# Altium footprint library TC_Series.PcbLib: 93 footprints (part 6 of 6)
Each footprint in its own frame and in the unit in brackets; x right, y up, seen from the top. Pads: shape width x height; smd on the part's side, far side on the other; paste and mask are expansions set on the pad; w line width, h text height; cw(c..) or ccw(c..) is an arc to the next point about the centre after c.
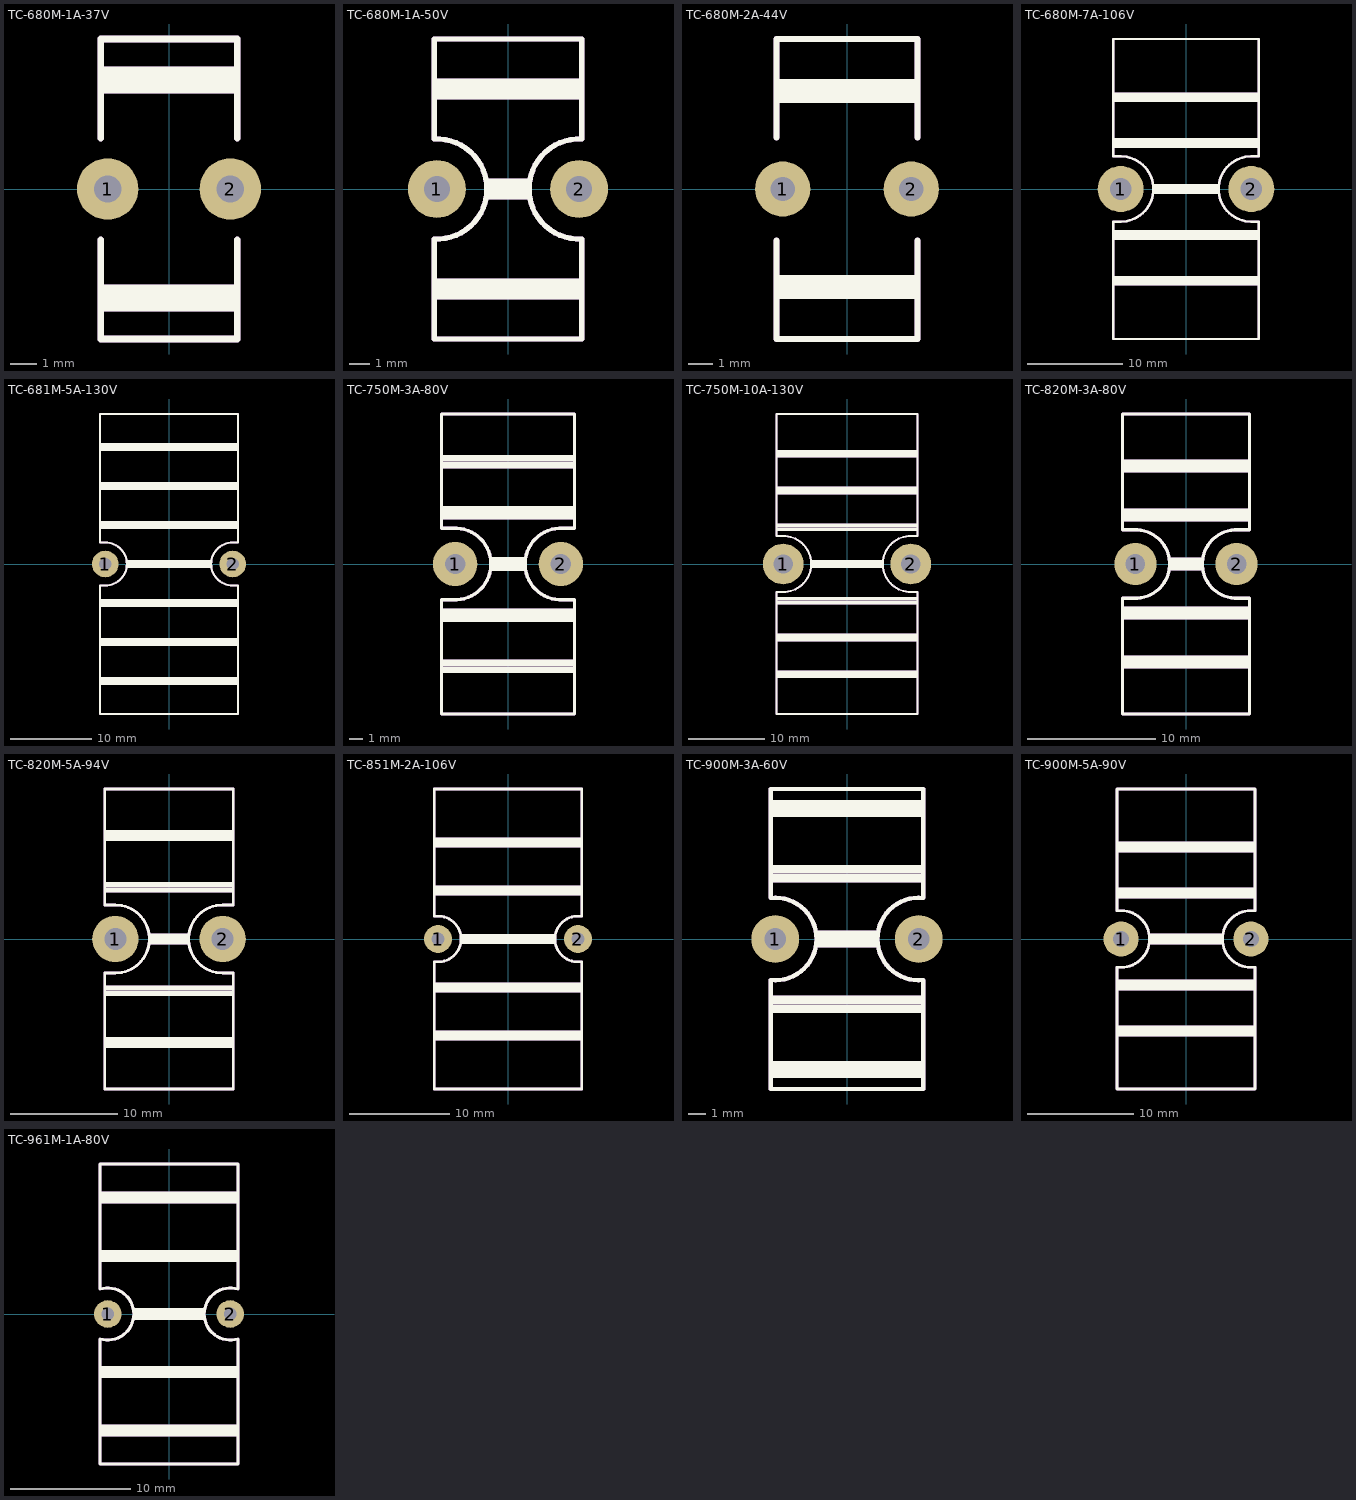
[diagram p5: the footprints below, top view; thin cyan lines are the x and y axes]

## TC-680M-1A-37V [mil]
pads (2):
  round 90 hole 40: 1(-90,0) 2(90,0)
Top Overlay:
  lines w10: -100,-74.78 -100,-220 100,-220 100,-74.78 ; -100,74.78 -100,220 100,220 100,74.78
  lines w19.68: -95,-170 95,-170 ; -95,-150 95,-150 ; -95,150 95,150 ; -95,170 95,170
Mechanical 29:
  lines w10: -100,-74.78 -100,-220 100,-220 100,-74.78 ; -100,74.78 -100,220 100,220 100,74.78
  lines w19.68: -95,-170 95,-170 ; -95,-150 95,-150 ; -95,150 95,150 ; -95,170 95,170
  text "'.Designator'" at -785,-42.45 h200

## TC-680M-1A-50V [mil]
pads (2):
  round 110 hole 50: 1(-135,0) 2(135,0)
Top Overlay:
  lines w10: 140,-95 140,-285 -140,-285 -140,-94.87 ccw(c-135,0) -139.99,94.87 -140,285 140,285 140,95 ; 139.99,-94.87 cw(c135,0) 139.99,94.87
  lines w19.68: -135,-200 135,-200 ; -135,-180 135,-180 ; -135,180 135,180 ; -135,200 135,200 ; -35,-10 35,-10 ; -35,10 35,10
Mechanical 29:
  lines w10: 140,-95 140,-285 -140,-285 -140,-94.87 ccw(c-135,0) -139.99,94.87 -140,285 140,285 140,95 ; 139.99,-94.87 cw(c135,0) 139.99,94.87
  lines w19.68: -135,-200 135,-200 ; -135,-180 135,-180 ; -135,180 135,180 ; -135,200 135,200 ; -35,-10 35,-10 ; -35,10 35,10
  text "'.Designator'" at -1750,-64.85 h400

## TC-680M-2A-44V [mil]
pads (2):
  round 90 hole 40: 1(-105,0) 2(105,0)
Top Overlay:
  lines w10: -115,-84.42 -115,-245 115,-245 115,-84.42 ; -115,84.42 -115,245 115,245 115,84.42
  lines w19.68: -110,-170 110,-170 ; -110,-150 110,-150 ; -110,150 110,150 ; -110,170 110,170
Mechanical 29:
  lines w10: -115,-84.42 -115,-245 115,-245 115,-84.42 ; -115,84.42 -115,245 115,245 115,84.42
  lines w19.68: -110,-170 110,-170 ; -110,-150 110,-150 ; -110,150 110,150 ; -110,170 110,170
  text "'.Designator'" at -1750,-64.85 h400

## TC-680M-7A-106V [mil]
pads (2):
  round 190 hole 90: 1(-270,0) 2(270,0)
Top Overlay:
  lines w10: -300,-620 300,-620 300,-135 270,-135 cw(c270,0) 270,135 300,135 300,620 -300,620 -300,135 -270,135 cw(c-270,0) -270,-135 -300,-135 -300,-620
  lines w19.68: -295,-390 295,-390 ; -295,-370 295,-370 ; -295,-200 295,-200 ; -295,-180 295,-180 ; -295,180 295,180 ; -295,200 295,200 ; -295,370 295,370 ; -295,390 295,390 ; -130,-10 130,-10 ; -130,10 130,10
Mechanical 29:
  lines w10: -300,-620 300,-620 300,-135 270,-135 cw(c270,0) 270,135 300,135 300,620 -300,620 -300,135 -270,135 cw(c-270,0) -270,-135 -300,-135 -300,-620
  lines w19.68: -295,-390 295,-390 ; -295,-370 295,-370 ; -295,-200 295,-200 ; -295,-180 295,-180 ; -295,180 295,180 ; -295,200 295,200 ; -295,370 295,370 ; -295,390 295,390 ; -130,-10 130,-10 ; -130,10 130,10
  text "'.Designator'" at -1750,-64.85 h400

## TC-681M-5A-130V [mil]
pads (2):
  round 130 hole 60: 1(-310,0) 2(310,0)
Top Overlay:
  lines w10: -335,-730 335,-730 335,-105 310,-105 cw(c310,0) 310,105 335,105 335,730 -335,730 -335,105 -310,105 cw(c-310,0) -310,-105 -335,-105 -335,-730
  lines w19.68: -330,-580 330,-580 ; -330,-560 330,-560 ; -330,-390 330,-390 ; -330,-370 330,-370 ; -330,-200 330,-200 ; -330,-180 330,-180 ; -330,180 330,180 ; -330,200 330,200 ; -330,370 330,370 ; -330,390 330,390 ; -330,560 330,560 ; -330,580 330,580 ; -200,-10 200,-10 ; -200,10 200,10
Mechanical 29:
  lines w10: -335,-730 335,-730 335,-105 310,-105 cw(c310,0) 310,105 335,105 335,730 -335,730 -335,105 -310,105 cw(c-310,0) -310,-105 -335,-105 -335,-730
  lines w19.68: -330,-580 330,-580 ; -330,-560 330,-560 ; -330,-390 330,-390 ; -330,-370 330,-370 ; -330,-200 330,-200 ; -330,-180 330,-180 ; -330,180 330,180 ; -330,200 330,200 ; -330,370 330,370 ; -330,390 330,390 ; -330,560 330,560 ; -330,580 330,580 ; -200,-10 200,-10 ; -200,10 200,10
  text "'.Designator'" at -1750,-64.85 h400

## TC-750M-3A-80V [mil]
pads (2):
  round 130 hole 60: 1(-155,0) 2(155,0)
Top Overlay:
  lines w10: -195,-105 -195,-440 195,-440 195,-105 ; -195,105 -195,440 195,440 195,105 ; -194.85,-104.85 -160.52,-104.85 ccw(c-155,0) -160.52,104.85 -194.85,104.85 ; 194.85,-104.85 160.52,-104.85 cw(c155,0) 160.52,104.85 194.85,104.85
  lines w19.68: -190,-310 190,-310 ; -190,-290 190,-290 ; -190,-160 190,-160 ; -190,-140 190,-140 ; -190,140 190,140 ; -190,160 190,160 ; -190,290 190,290 ; -190,310 190,310 ; -45,-10 45,-10 ; -45,10 45,10
Mechanical 29:
  lines w10: -195,-105 -195,-440 195,-440 195,-105 ; -195,105 -195,440 195,440 195,105 ; -194.85,-104.85 -160.52,-104.85 ccw(c-155,0) -160.52,104.85 -194.85,104.85 ; 194.85,-104.85 160.52,-104.85 cw(c155,0) 160.52,104.85 194.85,104.85
  lines w19.68: -190,-310 190,-310 ; -190,-290 190,-290 ; -190,-160 190,-160 ; -190,-140 190,-140 ; -190,140 190,140 ; -190,160 190,160 ; -190,290 190,290 ; -190,310 190,310 ; -45,-10 45,-10 ; -45,10 45,10
  text "'.Designator'" at -1750,-64.85 h400

## TC-750M-10A-130V [mil]
pads (2):
  round 210 hole 100: 1(-330,0) 2(330,0)
Top Overlay:
  lines w10: -365,-775 -365,-145 -330,-145 ccw(c-330,0) -330,145 -365,145 -365,775 365,775 365,145 330,145 ccw(c330,0) 330,-145 365,-145 365,-775 -365,-775
  lines w19.68: -360,-580 360,-580 ; -360,-560 360,-560 ; -360,-390 360,-390 ; -360,-370 360,-370 ; -360,-200 360,-200 ; -360,-180 360,-180 ; -360,180 360,180 ; -360,200 360,200 ; -360,370 360,370 ; -360,390 360,390 ; -360,560 360,560 ; -360,580 360,580 ; -180,-10 180,-10 ; -180,10 180,10
Mechanical 29:
  lines w10: -365,-775 -365,-145 -330,-145 ccw(c-330,0) -330,145 -365,145 -365,775 365,775 365,145 330,145 ccw(c330,0) 330,-145 365,-145 365,-775 -365,-775
  lines w19.68: -360,-580 360,-580 ; -360,-560 360,-560 ; -360,-390 360,-390 ; -360,-370 360,-370 ; -360,-200 360,-200 ; -360,-180 360,-180 ; -360,180 360,180 ; -360,200 360,200 ; -360,370 360,370 ; -360,390 360,390 ; -360,560 360,560 ; -360,580 360,580 ; -180,-10 180,-10 ; -180,10 180,10
  text "'.Designator'" at -1750,-64.85 h400

## TC-820M-3A-80V [mil]
pads (2):
  round 130 hole 60: 1(-155,0) 2(155,0)
Top Overlay:
  lines w10: -195,-105 -195,-460 195,-460 195,-105 ; -195,105 -195,460 195,460 195,105 ; -194.85,-104.85 -160.52,-104.85 ccw(c-155,0) -160.52,104.85 -194.85,104.85 ; 194.85,-104.85 160.52,-104.85 cw(c155,0) 160.52,104.85 194.85,104.85
  lines w19.68: -190,-310 190,-310 ; -190,-290 190,-290 ; -190,-160 190,-160 ; -190,-140 190,-140 ; -190,140 190,140 ; -190,160 190,160 ; -190,290 190,290 ; -190,310 190,310 ; -45,-10 45,-10 ; -45,10 45,10
Mechanical 29:
  lines w10: -195,-105 -195,-460 195,-460 195,-105 ; -195,105 -195,460 195,460 195,105 ; -194.85,-104.85 -160.52,-104.85 ccw(c-155,0) -160.52,104.85 -194.85,104.85 ; 194.85,-104.85 160.52,-104.85 cw(c155,0) 160.52,104.85 194.85,104.85
  lines w19.68: -190,-310 190,-310 ; -190,-290 190,-290 ; -190,-160 190,-160 ; -190,-140 190,-140 ; -190,140 190,140 ; -190,160 190,160 ; -190,290 190,290 ; -190,310 190,310 ; -45,-10 45,-10 ; -45,10 45,10
  text "'.Designator'" at -1750,-64.85 h400

## TC-820M-5A-94V [mil]
pads (2):
  round 170 hole 80: 1(-197,0) 2(197,0)
Top Overlay:
  lines w10: -236,-551 236,-551 236,-125 197,-125 cw(c197,0) 197,125 236,125 236,551 -236,551 -236,125 -197,125 cw(c-197,0) -197,-125 -236,-125 -236,-551
  lines w19.68: -230,-390 230,-390 ; -230,-370 230,-370 ; -230,-200 230,-200 ; -230,-180 230,-180 ; -230,180 230,180 ; -230,200 230,200 ; -230,370 230,370 ; -230,390 230,390 ; -67,-10 68,-10 ; -67,10 68,10
Mechanical 29:
  lines w10: -236,-551 236,-551 236,-125 197,-125 cw(c197,0) 197,125 236,125 236,551 -236,551 -236,125 -197,125 cw(c-197,0) -197,-125 -236,-125 -236,-551
  lines w19.68: -230,-390 230,-390 ; -230,-370 230,-370 ; -230,-200 230,-200 ; -230,-180 230,-180 ; -230,180 230,180 ; -230,200 230,200 ; -230,370 230,370 ; -230,390 230,390 ; -67,-10 68,-10 ; -67,10 68,10
  text "'.Designator'" at -1750,-64.85 h400

## TC-851M-2A-106V [mil]
pads (2):
  round 110 hole 50: 1(-275,0) 2(275,0)
Top Overlay:
  lines w10: 290,88.63 290,590 -290,590 -290,88.74 cw(c-275,0) -290,-88.74 -290,-590 290,-590 290,-88.74 cw(c275,0) 290,88.74
  lines w19.68: -285,-390 285,-390 ; -285,-370 285,-370 ; -285,-200 285,-200 ; -285,-180 285,-180 ; -285,180 285,180 ; -285,200 285,200 ; -285,370 285,370 ; -285,390 285,390 ; -180,-10 180,-10 ; -180,10 180,10
Mechanical 29:
  lines w10: 290,88.63 290,590 -290,590 -290,88.74 cw(c-275,0) -290,-88.74 -290,-590 290,-590 290,-88.74 cw(c275,0) 290,88.74
  lines w19.68: -285,-390 285,-390 ; -285,-370 285,-370 ; -285,-200 285,-200 ; -285,-180 285,-180 ; -285,180 285,180 ; -285,200 285,200 ; -285,370 285,370 ; -285,390 285,390 ; -180,-10 180,-10 ; -180,10 180,10
  text "'.Designator'" at -1750,-64.85 h400

## TC-900M-3A-60V [mil]
pads (2):
  round 110 hole 50: 1(-165,0) 2(165,0)
Top Overlay:
  lines w10: -175,-94.48 -175,-345 175,-345 175,-95 ; -175,-94.47 ccw(c-165,0) -174.95,94.48 ; -175,94.48 -175,345 175,345 175,95 ; 174.95,-94.48 cw(c165,0) 174.93,94.48
  lines w19.68: -170,-310 170,-310 ; -170,-290 170,-290 ; -170,-160 170,-160 ; -170,-140 170,-140 ; -170,140 170,140 ; -170,160 170,160 ; -170,290 170,290 ; -170,310 170,310 ; -65,-10 65,-10 ; -65,10 65,10
Mechanical 29:
  lines w10: -175,-94.48 -175,-345 175,-345 175,-95 ; -175,-94.47 ccw(c-165,0) -174.95,94.48 ; -175,94.48 -175,345 175,345 175,95 ; 174.95,-94.48 cw(c165,0) 174.93,94.48
  lines w19.68: -170,-310 170,-310 ; -170,-290 170,-290 ; -170,-160 170,-160 ; -170,-140 170,-140 ; -170,140 170,140 ; -170,160 170,160 ; -170,290 170,290 ; -170,310 170,310 ; -65,-10 65,-10 ; -65,10 65,10
  text "'.Designator'" at -1750,-64.85 h400

## TC-900M-5A-90V [mil]
pads (2):
  round 130 hole 60: 1(-240,0) 2(240,0)
Top Overlay:
  lines w10: -255,-555 255,-555 255,-105 240,-105 cw(c240,0) 240,105 255,105 255,555 -255,555 -255,105 -240,105 cw(c-240,0) -240,-105 -255,-105 -255,-555
  lines w19.68: -250,-350 250,-350 ; -250,-330 250,-330 ; -250,-180 250,-180 ; -250,-160 250,-160 ; -250,160 250,160 ; -250,180 250,180 ; -250,330 250,330 ; -250,350 250,350 ; -130,-10 130,-10 ; -130,10 130,10
Mechanical 29:
  lines w10: -255,-555 255,-555 255,-105 240,-105 cw(c240,0) 240,105 255,105 255,555 -255,555 -255,105 -240,105 cw(c-240,0) -240,-105 -255,-105 -255,-555
  lines w19.68: -250,-350 250,-350 ; -250,-330 250,-330 ; -250,-180 250,-180 ; -250,-160 250,-160 ; -250,160 250,160 ; -250,180 250,180 ; -250,330 250,330 ; -250,350 250,350 ; -130,-10 130,-10 ; -130,10 130,10
  text "'.Designator'" at -1750,-64.85 h400

## TC-961M-1A-80V [mil]
pads (2):
  round 90 hole 42: 1(-200,0) 2(200,0)
Top Overlay:
  lines w10: -225,-81.24 ccw(c-200,0) -225,81.24 -225,490 225,490 225,81.35 ; -225,-81.13 -225,-490 225,-490 225,-81.55 ; 224.91,-81.27 cw(c200,0) 224.97,81.25
  lines w19.68: -220,-390 220,-390 ; -220,-370 220,-370 ; -220,-200 220,-200 ; -220,-180 220,-180 ; -220,180 220,180 ; -220,200 220,200 ; -220,370 220,370 ; -220,390 220,390 ; -110,-10 110,-10 ; -110,10 110,10
Mechanical 29:
  lines w10: -225,-81.24 ccw(c-200,0) -225,81.24 -225,490 225,490 225,81.35 ; -225,-81.13 -225,-490 225,-490 225,-81.55 ; 224.91,-81.27 cw(c200,0) 224.97,81.25
  lines w19.68: -220,-390 220,-390 ; -220,-370 220,-370 ; -220,-200 220,-200 ; -220,-180 220,-180 ; -220,180 220,180 ; -220,200 220,200 ; -220,370 220,370 ; -220,390 220,390 ; -110,-10 110,-10 ; -110,10 110,10
  text "'.Designator'" at -1750,-64.85 h400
